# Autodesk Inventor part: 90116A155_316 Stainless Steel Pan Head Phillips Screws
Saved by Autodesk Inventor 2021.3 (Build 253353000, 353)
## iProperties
Created: 2022-05
Part Number: 90116A155_316 Stainless Steel Pan Head Phillips Screws
Material: Generic
Document SubType Name: Modeling
Designer: Administrator
Density: 1 g/cm^3
Appearance: Default
Title: 90116A155_316 Stainless Steel Pan Head Phillips Screws
Author: Administrator
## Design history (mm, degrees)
feature "Body1"
body "Solid1"
